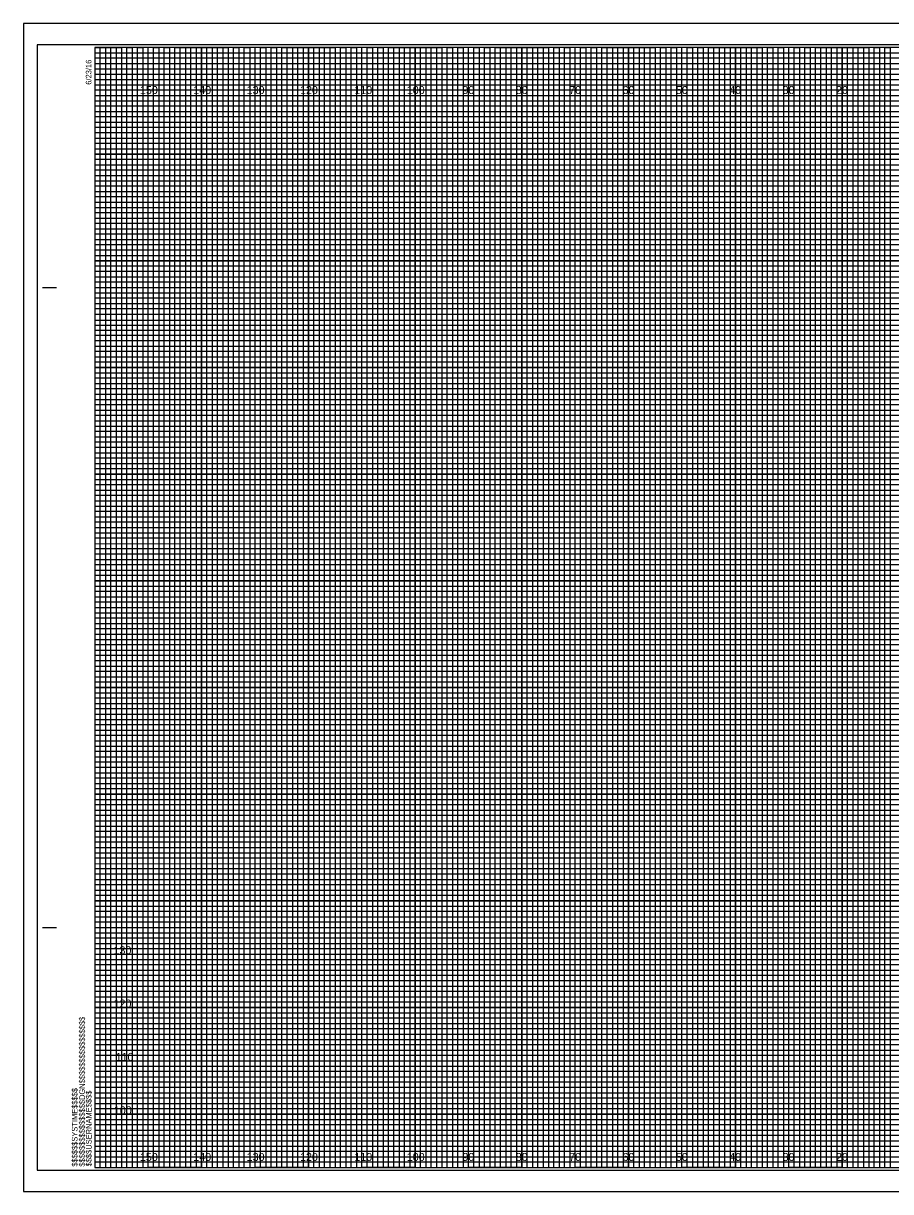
# Model space of a CAD drawing. Extents: x -13 to 323, y -5 to 434.
# Drawn here: x -13.4 to 149.1, y 215.5 to 434.5 of the extents above; entities that cross this region are included whole.
import ezdxf

# ---------------------------------------------------------------- set-up
doc = ezdxf.new("R2010")
doc.units = 0
for name, color, linetype in [('Exist Cross Section Cell', 7, 'Continuous'), ('Exist XS Center Line Elevation Label', 7, 'Continuous'), ('Exist XS Ground Line', 7, 'Continuous'), ('Prop CMT Pvmt Course 1 Wedge', 7, 'Continuous'), ('Prop CMT Pvmt Course 2', 7, 'Continuous'), ('Prop CMT Pvmt Course 2 Wedge', 7, 'Continuous'), ('Prop CMT Pvmt Course 3', 7, 'Continuous'), ('Prop CMT Shld Paved Course 1', 7, 'Continuous'), ('Prop CMT Shld Paved Course 2', 7, 'Continuous'), ('Prop CMT Subgrade Earthwork', 7, 'Continuous'), ('Scratch_Level_0', 7, 'Continuous')]:
    doc.layers.add(name, color=color, linetype=linetype)

msp = doc.modelspace()

# ---------------------------------------------------------------- linework, layer by layer
at = {"layer": 'Exist XS Center Line Elevation Label'}
for points in [[(0, 430), (5, 430), (5, 220), (15, 220), (15, 430), (25, 430), (25, 220), (35, 220), (35, 430), (45, 430), (45, 220), (55, 220), (55, 430), (65, 430), (65, 220), (75, 220), (75, 430), (85, 430), (85, 220), (95, 220), (95, 430), (105, 430), (105, 220), (115, 220), (115, 430), (125, 430), (125, 220), (135, 220), (135, 430), (145, 430), (145, 220), (155, 220)], [(0, 425), (275, 425)], [(0, 405), (320, 405), (320, 415), (0, 415)], [(0, 385), (320, 385), (320, 395), (0, 395)], [(0, 365), (320, 365), (320, 375), (0, 375)], [(0, 345), (320, 345), (320, 355), (0, 355)], [(0, 325), (320, 325), (320, 335), (0, 335)], [(0, 305), (320, 305), (320, 315), (0, 315)], [(0, 285), (320, 285), (320, 295), (0, 295)], [(0, 265), (320, 265), (320, 275), (0, 275)], [(0, 245), (320, 245), (320, 255), (0, 255)], [(0, 225), (320, 225), (320, 235), (0, 235)]]:
    msp.add_lwpolyline(points, dxfattribs=at)
at = {"layer": 'Exist XS Ground Line'}
for p, q in [((10, 430), (0, 430)), ((10, 220), (10, 430)), ((30, 430), (20, 430)), ((20, 430), (20, 220)), ((30, 220), (30, 430)), ((50, 430), (40, 430)), ((40, 430), (40, 220)), ((50, 220), (50, 430)), ((70, 430), (60, 430)), ((60, 430), (60, 220)), ((70, 220), (70, 430)), ((90, 430), (80, 430)), ((80, 430), (80, 220)), ((90, 220), (90, 430)), ((110, 430), (100, 430)), ((100, 430), (100, 220)), ((110, 220), (110, 430)), ((130, 430), (120, 430)), ((120, 430), (120, 220)), ((130, 220), (130, 430)), ((150, 430), (140, 430)), ((140, 430), (140, 220)), ((20, 220), (10, 220)), ((40, 220), (30, 220)), ((60, 220), (50, 220)), ((80, 220), (70, 220)), ((100, 220), (90, 220)), ((120, 220), (110, 220)), ((140, 220), (130, 220))]:
    msp.add_line(p, q, dxfattribs=at)
for points in [[(0, 420), (320, 420), (320, 410), (0, 410)], [(0, 400), (320, 400), (320, 390), (0, 390)], [(0, 380), (320, 380), (320, 370), (0, 370)], [(0, 360), (320, 360), (320, 350), (0, 350)], [(0, 340), (320, 340), (320, 330), (0, 330)], [(0, 320), (320, 320), (320, 310), (0, 310)], [(0, 300), (320, 300), (320, 290), (0, 290)], [(0, 280), (320, 280), (320, 270), (0, 270)], [(0, 260), (320, 260), (320, 250), (0, 250)], [(0, 240), (320, 240), (320, 230), (0, 230)]]:
    msp.add_lwpolyline(points, dxfattribs=at)
at = {"layer": 'Prop CMT Pvmt Course 1 Wedge'}
for p, q in [((323.3, 434.5), (-13.4, 434.5)), ((-13.4, 434.5), (-13.4, 215.5)), ((-13.4, 215.5), (323.3, 215.5))]:
    msp.add_line(p, q, dxfattribs=at)
at = {"layer": 'Prop CMT Pvmt Course 2'}
msp.add_lwpolyline([(-13.4, 215.5), (323.3, 215.5), (323.3, 434.5), (-13.4, 434.5)], close=True, dxfattribs=at)
at = {"layer": 'Prop CMT Pvmt Course 3'}
msp.add_lwpolyline([(-10.8, 219.5), (322.4, 219.5), (322.4, 430.5), (-10.8, 430.5)], close=True, dxfattribs=at)
at = {"layer": 'Prop CMT Shld Paved Course 1'}
for p, q in [((-9.8, 385), (-7.3, 385)), ((-9.7, 385), (-7.2, 385)), ((-9.8, 265), (-7.3, 265)), ((-9.7, 265), (-7.2, 265)), ((0, 220), (0, 220)), ((0, 220), (0, 220)), ((0, 220), (0, 220)), ((0, 220), (0, 220)), ((0, 220), (0, 220)), ((0, 220), (0, 220)), ((0, 220), (0, 220))]:
    msp.add_line(p, q, dxfattribs=at)
msp.add_lwpolyline([(320, 430), (0, 430), (0, 220), (320, 220)], close=True, dxfattribs=at)
at = {"layer": 'Prop CMT Shld Paved Course 2'}
for points in [[(0, 220), (1, 220), (1, 430), (2, 430), (2, 220)], [(2, 220), (3, 220), (3, 430), (4, 430), (4, 220)], [(5, 220), (6, 220), (6, 430), (7, 430), (7, 220)], [(7, 220), (8, 220), (8, 430), (9, 430), (9, 220)], [(10, 220), (11, 220), (11, 430), (12, 430), (12, 220)], [(12, 220), (13, 220), (13, 430), (14, 430), (14, 220)], [(15, 220), (16, 220), (16, 430), (17, 430), (17, 220)], [(17, 220), (18, 220), (18, 430), (19, 430), (19, 220)], [(20, 220), (21, 220), (21, 430), (22, 430), (22, 220)], [(22, 220), (23, 220), (23, 430), (24, 430), (24, 220)], [(25, 220), (26, 220), (26, 430), (27, 430), (27, 220)], [(27, 220), (28, 220), (28, 430), (29, 430), (29, 220)], [(30, 220), (31, 220), (31, 430), (32, 430), (32, 220)], [(32, 220), (33, 220), (33, 430), (34, 430), (34, 220)], [(35, 220), (36, 220), (36, 430), (37, 430), (37, 220)], [(37, 220), (38, 220), (38, 430), (39, 430), (39, 220)], [(40, 220), (41, 220), (41, 430), (42, 430), (42, 220)], [(42, 220), (43, 220), (43, 430), (44, 430), (44, 220)], [(45, 220), (46, 220), (46, 430), (47, 430), (47, 220)], [(47, 220), (48, 220), (48, 430), (49, 430), (49, 220)], [(50, 220), (51, 220), (51, 430), (52, 430), (52, 220)], [(52, 220), (53, 220), (53, 430), (54, 430), (54, 220)], [(55, 220), (56, 220), (56, 430), (57, 430), (57, 220)], [(57, 220), (58, 220), (58, 430), (59, 430), (59, 220)], [(60, 220), (61, 220), (61, 430), (62, 430), (62, 220)], [(62, 220), (63, 220), (63, 430), (64, 430), (64, 220)], [(65, 220), (66, 220), (66, 430), (67, 430), (67, 220)], [(67, 220), (68, 220), (68, 430), (69, 430), (69, 220)], [(70, 220), (71, 220), (71, 430), (72, 430), (72, 220)], [(72, 220), (73, 220), (73, 430), (74, 430), (74, 220)], [(75, 220), (76, 220), (76, 430), (77, 430), (77, 220)], [(77, 220), (78, 220), (78, 430), (79, 430), (79, 220)], [(80, 220), (81, 220), (81, 430), (82, 430), (82, 220)], [(82, 220), (83, 220), (83, 430), (84, 430), (84, 220)], [(85, 220), (86, 220), (86, 430), (87, 430), (87, 220)], [(87, 220), (88, 220), (88, 430), (89, 430), (89, 220)], [(90, 220), (91, 220), (91, 430), (92, 430), (92, 220)], [(92, 220), (93, 220), (93, 430), (94, 430), (94, 220)], [(95, 220), (96, 220), (96, 430), (97, 430), (97, 220)], [(97, 220), (98, 220), (98, 430), (99, 430), (99, 220)], [(100, 220), (101, 220), (101, 430), (102, 430), (102, 220)], [(102, 220), (103, 220), (103, 430), (104, 430), (104, 220)], [(105, 220), (106, 220), (106, 430), (107, 430), (107, 220)], [(107, 220), (108, 220), (108, 430), (109, 430), (109, 220)], [(110, 220), (111, 220), (111, 430), (112, 430), (112, 220)], [(112, 220), (113, 220), (113, 430), (114, 430), (114, 220)], [(115, 220), (116, 220), (116, 430), (117, 430), (117, 220)], [(117, 220), (118, 220), (118, 430), (119, 430), (119, 220)], [(120, 220), (121, 220), (121, 430), (122, 430), (122, 220)], [(122, 220), (123, 220), (123, 430), (124, 430), (124, 220)], [(125, 220), (126, 220), (126, 430), (127, 430), (127, 220)], [(127, 220), (128, 220), (128, 430), (129, 430), (129, 220)], [(130, 220), (131, 220), (131, 430), (132, 430), (132, 220)], [(132, 220), (133, 220), (133, 430), (134, 430), (134, 220)], [(135, 220), (136, 220), (136, 430), (137, 430), (137, 220)], [(137, 220), (138, 220), (138, 430), (139, 430), (139, 220)], [(140, 220), (141, 220), (141, 430), (142, 430), (142, 220)], [(142, 220), (143, 220), (143, 430), (144, 430), (144, 220)], [(145, 220), (146, 220), (146, 430), (147, 430), (147, 220)], [(147, 220), (148, 220), (148, 430), (149, 430), (149, 220)]]:
    msp.add_lwpolyline(points, dxfattribs=at)
at = {"layer": 'Prop CMT Subgrade Earthwork'}
for p, q in [((10, 220), (10, 430)), ((20, 220), (20, 430)), ((30, 220), (30, 430)), ((40, 220), (40, 430)), ((50, 220), (50, 430)), ((60, 220), (60, 430)), ((70, 220), (70, 430)), ((80, 220), (80, 430)), ((90, 220), (90, 430)), ((100, 220), (100, 430)), ((110, 220), (110, 430)), ((120, 220), (120, 430)), ((130, 220), (130, 430)), ((140, 220), (140, 430)), ((0, 420), (320, 420)), ((0, 410), (320, 410)), ((0, 400), (320, 400)), ((0, 390), (320, 390)), ((0, 380), (320, 380)), ((0, 370), (320, 370)), ((0, 360), (320, 360)), ((0, 350), (320, 350)), ((0, 340), (320, 340)), ((0, 330), (320, 330)), ((0, 320), (320, 320)), ((0, 310), (320, 310)), ((0, 300), (320, 300)), ((0, 290), (320, 290)), ((0, 280), (320, 280)), ((0, 270), (320, 270)), ((0, 260), (320, 260)), ((0, 250), (320, 250)), ((0, 240), (320, 240)), ((0, 230), (320, 230))]:
    msp.add_line(p, q, dxfattribs=at)
at = {"layer": 'Scratch_Level_0'}
for p, q in [((0, 429), (260, 429)), ((260, 427.98), (0, 427.98)), ((0, 427.98), (0, 427)), ((0, 427), (260, 427)), ((260, 425.89), (0, 425.89)), ((0, 425.89), (0, 424)), ((0, 424), (320, 424))]:
    msp.add_line(p, q, dxfattribs=at)
for points in [[(0, 423), (270, 423), (320, 423), (320, 422), (0, 422)], [(0, 421), (320, 421), (320, 419), (0, 419)], [(0, 418), (320, 418), (320, 417), (0, 416.98)], [(0, 416), (320, 416), (320, 414), (0, 414)], [(0, 413), (320, 413), (320, 412), (0, 412)], [(0, 411), (320, 411), (320, 409), (0, 409)], [(0, 408), (320, 408), (320, 407), (0, 407)], [(0, 406), (320, 406), (320, 404), (0, 404)], [(0, 403), (320, 403), (320, 402), (0, 402)], [(0, 401), (320, 401), (320, 399), (0, 399)], [(0, 398), (320, 398), (320, 397), (0, 397)], [(0, 396), (320, 396), (320, 393.95), (320, 393), (320, 392), (0, 392)], [(0, 394), (320, 394), (320, 393), (0, 393)], [(0, 391), (320, 391), (320, 389), (0, 389.03)], [(0, 389.03), (320, 389), (320, 388), (0, 388)], [(0, 387), (320, 387), (320, 386), (0, 386)], [(0, 384), (320, 384), (320, 383), (0, 383)], [(0, 382), (320, 382), (320, 381), (0, 381)], [(-0.07, 378.89), (320, 378.89), (320, 377.88), (-0.07, 377.88)], [(0, 377), (320, 377), (320, 376), (0, 376)], [(0, 374), (320, 374), (320, 373), (0, 373)], [(0, 372), (320, 372), (320, 371), (0, 371)], [(0, 369), (320, 369), (320, 368), (0, 368)], [(0, 367), (320, 367), (320, 366), (0, 366)], [(0, 364), (320, 364), (320, 363), (0, 363)], [(0, 362), (320, 362), (320, 361), (0, 361)], [(0, 359), (320, 359), (319.99, 357.98), (0, 358)], [(0, 357), (320, 357), (320, 356), (0, 356)], [(0, 354), (320, 354), (320, 353), (0, 353)], [(0, 352), (320, 352), (320, 351), (0, 351)], [(0, 349), (320, 349), (320, 348), (0, 348)], [(0, 347), (320, 347), (320, 346), (0, 346)], [(0, 344), (320, 344), (320, 343), (0, 343)], [(0, 342), (320, 342), (320, 341), (0, 341)], [(0, 339), (320, 339), (320, 338), (0, 338)], [(0, 336.99), (320.07, 336.91), (320, 336), (0, 336)], [(0, 334), (320, 334), (320, 333), (0, 333)], [(0, 332), (320, 332), (320, 331), (0, 331)], [(0, 329), (320, 329), (320, 328), (0, 328)], [(0, 327), (320, 327), (320, 326), (0, 326)], [(0, 324), (320, 324), (320, 323), (0, 323)], [(0, 322), (320, 322), (320, 321), (0, 321)], [(0, 319), (320, 319), (320, 318), (0, 318)], [(0, 317), (320, 317), (320, 316), (0, 316)], [(0, 314), (320, 314), (320, 313), (0, 313)], [(0, 312), (320, 312), (320, 311), (0, 311)], [(0, 309), (320, 309), (320, 308), (0, 308)], [(0, 307), (320, 307), (320, 306), (0, 306)], [(0, 304), (320, 304), (320, 303), (0, 303)], [(0, 302), (320, 302), (320, 301), (0, 301)], [(0, 299), (320, 299), (319.99, 297.98), (0, 298)], [(0, 297), (320, 297), (320, 296), (0, 296)], [(0, 294), (320, 294), (320, 293), (0, 293)], [(0, 292), (320, 292), (320, 291), (0, 291)], [(0, 289), (320, 289), (320, 288), (0, 288)], [(0, 287), (320, 287), (320, 286), (0, 286)], [(0, 284), (320, 284), (320, 283), (0, 283)], [(0, 282), (320, 282), (320, 281), (0, 281)], [(0, 279), (320, 279), (320, 278), (0, 278)], [(0, 276.99), (320.07, 276.91), (320, 276), (0, 276)], [(0, 274), (320, 274), (320, 273), (0, 273)], [(0, 272), (320, 272), (320, 271), (0, 271)], [(0, 269), (320, 269), (320, 268), (0, 268)], [(0, 267), (320, 267), (320, 266), (0, 266)], [(0, 264), (320, 264), (320, 263), (0, 263)], [(0, 262), (320, 262), (320, 261), (0, 261)], [(0, 259), (320, 259), (320, 258), (0, 258)], [(0, 257), (320, 257), (320, 256), (0, 256)], [(0, 254), (320, 254), (320, 253), (0, 253)], [(0, 252), (320, 252), (320, 251), (0, 251)], [(0, 249), (320, 249), (320, 248), (0, 248)], [(0, 247), (320, 247), (320, 246), (0, 246)], [(0, 244), (320, 244), (320, 243), (0, 243)], [(0, 242), (320, 242), (320, 241), (0, 241)], [(0, 239), (320, 239), (320, 238), (0, 238)], [(0, 237), (320, 237), (320, 236), (0, 236)], [(0, 234), (320, 234), (320, 233), (0, 233)], [(0, 232), (320, 232), (320, 231), (0, 231)], [(0, 229), (320, 229), (320, 228), (0, 228)], [(0, 227), (320, 227), (320, 226), (0, 226)], [(0, 224), (320, 224), (320, 223), (0, 223)], [(0, 222), (320, 222), (320, 221), (0, 221)]]:
    msp.add_lwpolyline(points, dxfattribs=at)

# ---------------------------------------------------------------- texts
at = {"layer": 'Exist Cross Section Cell'}
for s, p in [('150', (8.44, 421.25)), ('140', (18.44, 421.25)), ('130', (28.44, 421.25)), ('120', (38.44, 421.25)), ('110', (48.62, 421.25)), ('100', (58.44, 421.25)), ('90', (68.86, 421.25)), ('80', (78.86, 421.25)), ('70', (88.86, 421.25)), ('60', (98.86, 421.25)), ('50', (108.86, 421.25)), ('40', (118.86, 421.25)), ('30', (128.86, 421.25)), ('20', (138.86, 421.25)), ('150', (8.44, 221.25)), ('140', (18.44, 221.25)), ('130', (28.44, 221.25)), ('120', (38.44, 221.25)), ('110', (48.62, 221.25)), ('100', (58.44, 221.25)), ('90', (68.86, 221.25)), ('80', (78.86, 221.25)), ('70', (88.86, 221.25)), ('60', (98.86, 221.25)), ('50', (108.86, 221.25)), ('40', (118.86, 221.25)), ('30', (128.86, 221.25)), ('20', (138.86, 221.25))]:
    msp.add_text(s, height=1.5, dxfattribs=at).set_placement(p)
at = {"layer": 'Prop CMT Pvmt Course 2 Wedge'}
for s, p in [('130', (3.49, 260)), ('120', (3.5, 250)), ('110', (3.88, 240)), ('100', (3.55, 230))]:
    msp.add_text(s, height=1.5, dxfattribs=at).set_placement(p)
at = {"layer": 'Prop CMT Shld Paved Course 1'}
for s, p in [('6/23/16', (-0.65, 423)), ('$$$$$$$$$$$$$$$$DGN$$$$$$$$$$$$$$$$', (-1.88, 220.18)), ('$$$$$$SYSTIME$$$$$', (-3.26, 220.18)), ('$$$$USERNAME$$$$', (-0.62, 220.23))]:
    msp.add_text(s, height=1.05, rotation=90, dxfattribs=at).set_placement(p)

doc.saveas('drawing.dxf')
